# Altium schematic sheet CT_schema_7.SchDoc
size 274 x 160 mm
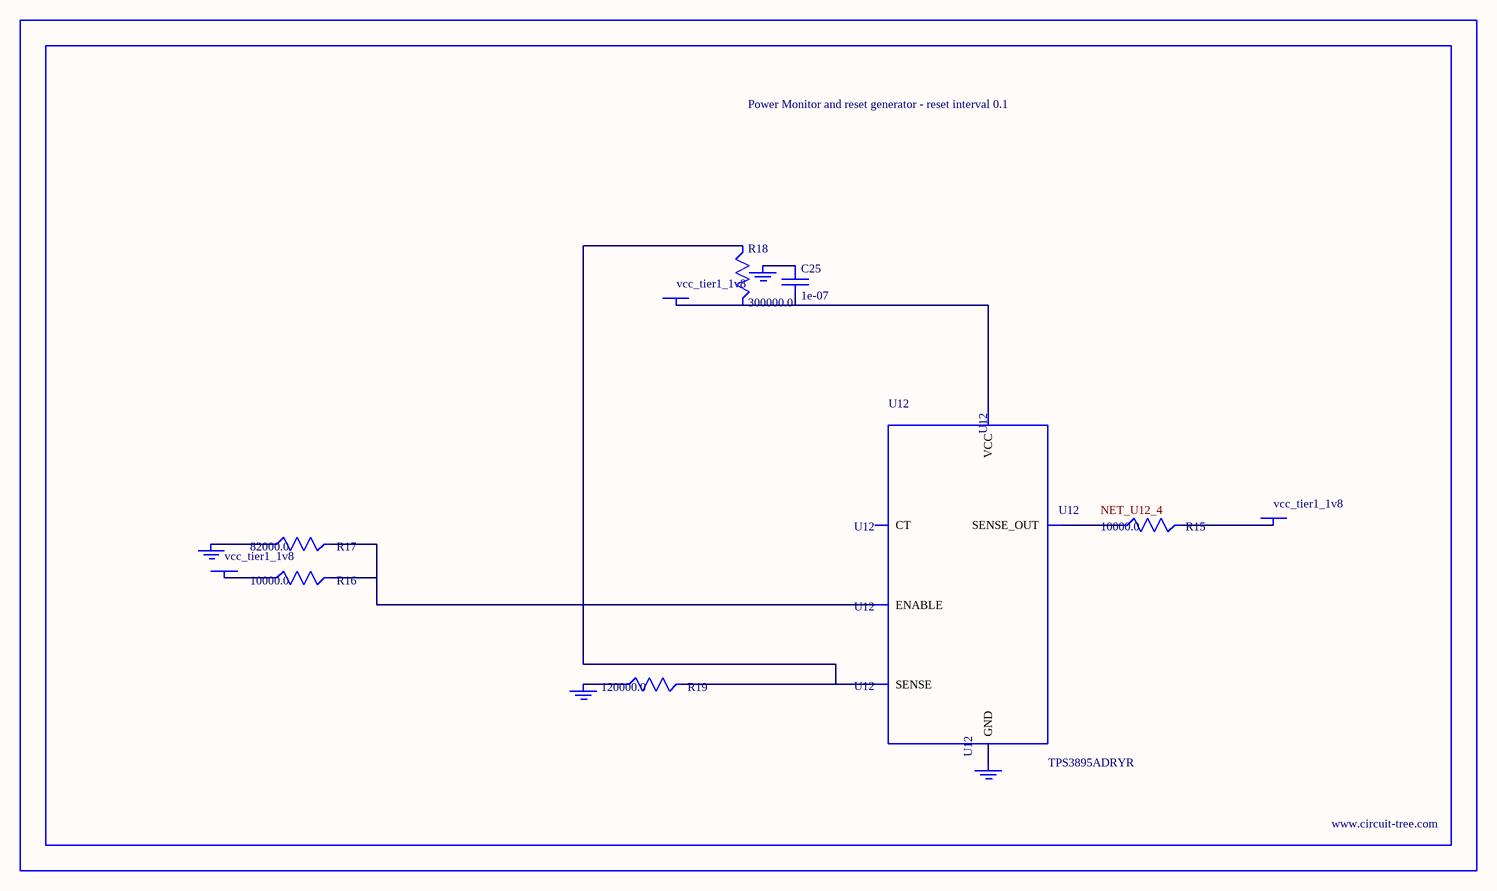
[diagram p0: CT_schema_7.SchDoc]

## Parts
BORDER6  (no value)
C25  1e-07  [C0402]
GND_INSTANCE_6_0  (no value)
GND_INSTANCE_6_1  (no value)
GND_INSTANCE_6_2  (no value)
GND_INSTANCE_6_3  (no value)
POWER_INSTANCE_6_0  vcc_tier1_1v8
POWER_INSTANCE_6_1  vcc_tier1_1v8
POWER_INSTANCE_6_2  vcc_tier1_1v8
R15  10000.0  [R0603]
R16  10000.0  [R0603]
R17  82000.0  [R0603]
R18  300000.0  [R0603]
R19  120000.0  [R0603]
U12  TPS3895ADRYR  [SON-6]

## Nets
NetC25_1: C25.1 GND_INSTANCE_6_2.0(GND)
NetC25_2: C25.2 POWER_INSTANCE_6_2.0(PWR) R18.2 U12.6(VCC)
NetGND_INSTANCE_6_0_0: GND_INSTANCE_6_0.0(GND) R17.1
NetGND_INSTANCE_6_1_0: GND_INSTANCE_6_1.0(GND) R19.1
NetGND_INSTANCE_6_3_0: GND_INSTANCE_6_3.0(GND) U12.2(GND)
NetPOWER_INSTANCE_6_0_0: POWER_INSTANCE_6_0.0(PWR) R16.1
NetPOWER_INSTANCE_6_1_0: POWER_INSTANCE_6_1.0(PWR) R15.2
NetR15_1: R15.1 U12.4(SENSE_OUT)
NetR16_2: R16.2 R17.2 U12.1(ENABLE)
NetR18_1: R18.1 R19.2 U12.3(SENSE)

Not connected (* = marked no-connect by the designer): U12 5(CT)

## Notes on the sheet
- Labels drawn without touching a wire or pin: NET_U12_4

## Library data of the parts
BORDER6 = BORDER_PAGE6
C25 = C0402C104K3RACTU
GND_INSTANCE_6_0-GND_INSTANCE_6_3 = GND
POWER_INSTANCE_6_0-POWER_INSTANCE_6_2 = PWR
R15 R16 = RC0603JR-0710KL
R17 = RC0603JR-0782KL
R18 = RC0603JR-07300KL
R19 = RC0603JR-07120KL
